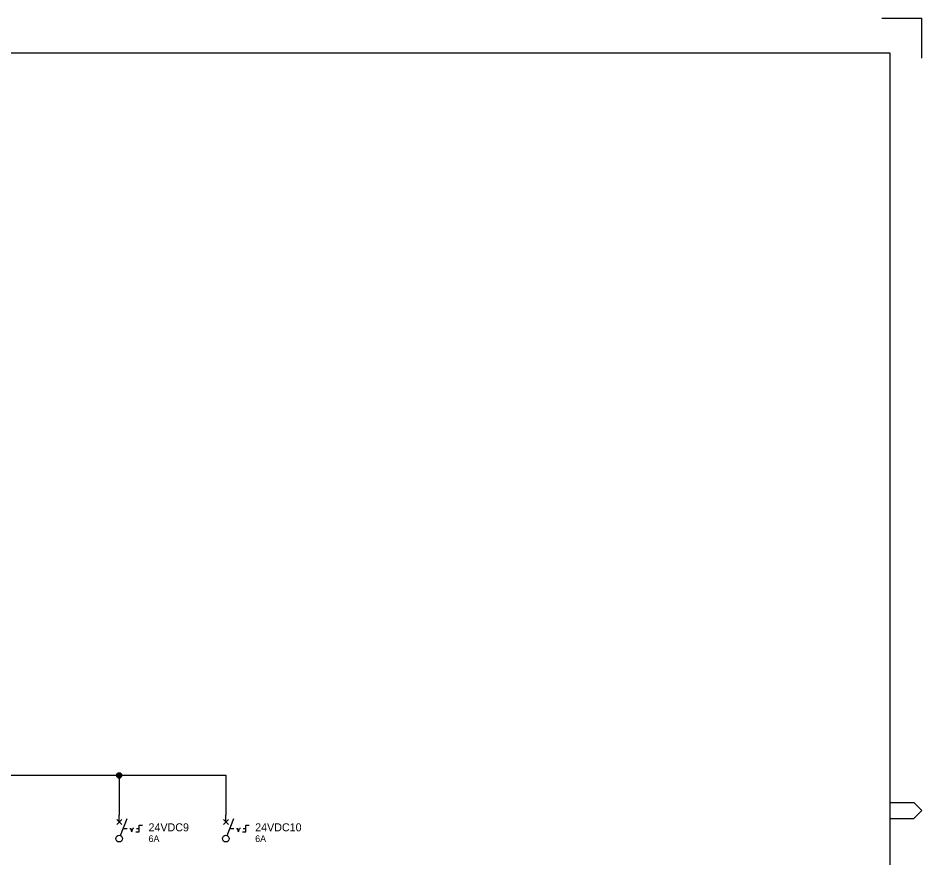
# Model space of a CAD drawing. Extents: x 0 to 841, y 0 to 594.
# Drawn here: x 502.1 to 841, y 279 to 594 of the extents above; entities that cross this region are included whole.
import ezdxf

# ---------------------------------------------------------------- set-up
doc = ezdxf.new("R2010")
doc.units = 0
for name, color, linetype in [('A1BORDER', 7, 'Continuous'), ('Level 1', 7, 'Continuous'), ('Level 10', 7, 'Continuous')]:
    doc.layers.add(name, color=color, linetype=linetype)

msp = doc.modelspace()

# ---------------------------------------------------------------- linework, layer by layer
at = {"layer": 'A1BORDER'}
for p, q in [((826, 594), (841, 594)), ((841, 579), (841, 594)), ((28, 581), (829, 581)), ((829, 581), (829, 15)), ((829, 299.76), (838, 299.76)), ((838, 299.76), (841, 296.76)), ((838, 293.76), (841, 296.76)), ((829, 293.76), (838, 293.76))]:
    msp.add_line(p, q, dxfattribs=at)
at = {"layer": 'Level 1'}
for p, q in [((80, 310), (580, 310)), ((540, 310), (540, 295)), ((580, 310), (580, 295)), ((540, 292.5), (540, 295)), ((580, 292.5), (580, 295)), ((539.06, 293.44), (540.94, 291.56)), ((540.94, 293.44), (539.06, 291.56)), ((540.46, 287.41), (543, 293.75)), ((579.06, 293.44), (580.94, 291.56)), ((580.94, 293.44), (579.06, 291.56)), ((580.46, 287.41), (583, 293.75))]:
    msp.add_line(p, q, dxfattribs=at)
for centre in [(540, 286.25), (580, 286.25)]:
    msp.add_circle(centre, 1.25, dxfattribs=at)
at = {"layer": 'Level 10'}
for p, q in [((539, 310), (540.99, 310)), ((539.05, 310.3), (540.95, 310.3)), ((539.05, 309.7), (540.95, 309.7)), ((539.2, 310.6), (540.8, 310.6)), ((539.2, 309.4), (540.8, 309.4)), ((539.56, 310.9), (540.44, 310.9)), ((539.56, 309.1), (540.44, 309.1)), ((540, 311), (540, 311)), ((541.5, 290), (543, 290)), ((544, 290), (544.33, 290)), ((544.75, 288.75), (544.33, 290)), ((544.75, 288.75), (545.17, 290)), ((545.5, 290), (545.17, 290)), ((546.25, 288.75), (547.5, 288.75)), ((546.5, 290), (547.5, 290)), ((547.5, 288.75), (547.5, 291.25)), ((547.5, 291.25), (548.75, 291.25)), ((581.5, 290), (583, 290)), ((584, 290), (584.33, 290)), ((584.75, 288.75), (584.33, 290)), ((584.75, 288.75), (585.17, 290)), ((585.5, 290), (585.17, 290)), ((586.25, 288.75), (587.5, 288.75)), ((586.5, 290), (587.5, 290)), ((587.5, 288.75), (587.5, 291.25)), ((587.5, 291.25), (588.75, 291.25))]:
    msp.add_line(p, q, dxfattribs=at)
msp.add_circle((540, 310), 1, dxfattribs=at)

# ---------------------------------------------------------------- texts
at = {"layer": 'Level 1'}
for s, height, p in [('24VDC9', 3, (551, 289)), ('24VDC10', 3, (591, 289)), ('6A', 2.5, (551, 285)), ('6A', 2.5, (591, 285))]:
    msp.add_text(s, height=height, dxfattribs=at).set_placement(p)

doc.saveas('drawing.dxf')
